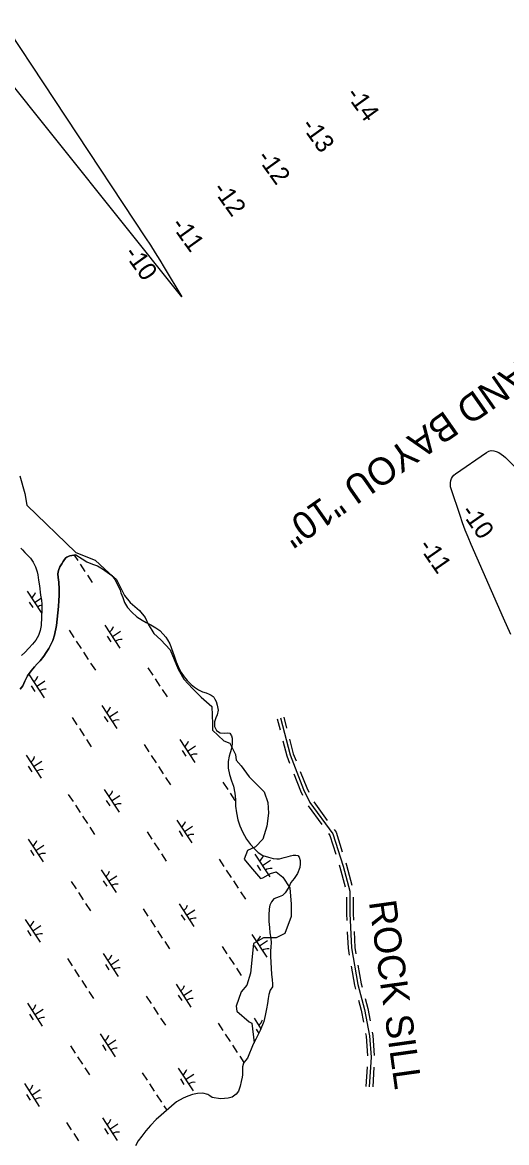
# Model space of a CAD drawing. Extents: x 3945642 to 3966284, y 206476 to 228921.
# Drawn here: x 3957171 to 3958060, y 213998 to 216052 of the extents above; entities that cross this region are included whole.
import ezdxf

# ---------------------------------------------------------------- set-up
doc = ezdxf.new("R2010")
doc.units = 0
for name, color, linetype in [('V-CHAN-NAID', 7, 'Continuous'), ('V-RIVR-EDGE', 7, 'Continuous'), ('V-RIVR-RANG', 7, 'Continuous'), ('V-RRAP-DIKE', 7, 'Continuous'), ('V-RRAP-SILL-IDEN', 7, 'Continuous'), ('V-TOPO-DPTH', 7, 'Continuous'), ('V-TOPO-MINR', 7, 'Continuous'), ('V-TOPO-SHOR', 7, 'Continuous'), ('V-WETL-SWMP', 7, 'Continuous')]:
    doc.layers.add(name, color=color, linetype=linetype)

msp = doc.modelspace()

# ---------------------------------------------------------------- linework, layer by layer
at = {"layer": 'V-RIVR-EDGE'}
for points in [[(3957166.7, 215220.6), (3957175.9, 215187.8), (3957179.8, 215166.7), (3957269.2, 215080)], [(3957269.2, 215080), (3957304.7, 215065.5), (3957330.9, 215041.9), (3957344.1, 215030.1), (3957358.5, 215001.1), (3957369, 214988), (3957386.1, 214973.5), (3957396.6, 214960.4), (3957401.9, 214948.6), (3957412.4, 214931.5), (3957425.6, 214919.7), (3957442.6, 214901.3), (3957457.1, 214865.8), (3957467.6, 214847.4), (3957483.4, 214830.3), (3957499.2, 214814.5), (3957518.9, 214797.4), (3957520.2, 214765.9), (3957520.2, 214754.1), (3957541.2, 214734.4), (3957551.7, 214730.4), (3957562.2, 214709.4), (3957563.5, 214698.9), (3957572.7, 214688.4), (3957587.2, 214668.7), (3957596.4, 214659.5), (3957614.8, 214641.1), (3957621.4, 214621.4), (3957622.7, 214601.6), (3957620.1, 214578), (3957612.2, 214554.3), (3957599, 214539.9), (3957584.6, 214533.3), (3957578, 214517.5), (3957589.8, 214503.1), (3957608.2, 214482), (3957612.2, 214483.4), (3957626.6, 214491.2), (3957637.1, 214493.9), (3957649, 214484.7), (3957662.1, 214465), (3957664.7, 214434.7), (3957664.7, 214412.4), (3957652.9, 214380.9), (3957637.1, 214373), (3957613.5, 214373), (3957595.1, 214362.5), (3957589.8, 214308.6), (3957583.3, 214286.2), (3957572.7, 214274.4), (3957563.5, 214248.1), (3957564.9, 214238.9), (3957587.2, 214219.2), (3957592.5, 214216.6), (3957596.3, 214180.5)]]:
    msp.add_lwpolyline(points, dxfattribs=at)
at = {"layer": 'V-RRAP-DIKE'}
for points in [[(3957638.8, 214775), (3957644.1, 214754.6)], [(3957644.9, 214776.5), (3957662.5, 214708.8), (3957687.2, 214645.5), (3957698.9, 214621.4), (3957741.2, 214563.9), (3957759.9, 214504.7), (3957772, 214459), (3957772, 214417.6), (3957775, 214354.9), (3957787, 214287.6), (3957799, 214242), (3957808, 214193.4), (3957811, 214154.3), (3957807.8, 214100.1)], [(3957650.9, 214778.1), (3957656.2, 214757.8)], [(3957649.4, 214734.3), (3957656.5, 214706.8), (3957661.7, 214693.5)], [(3957661.5, 214737.4), (3957668.4, 214710.7), (3957673.4, 214698)], [(3957669.4, 214673.9), (3957681.4, 214643), (3957685.5, 214634.6)], [(3957681, 214678.4), (3957692.9, 214648), (3957696.8, 214640.1)], [(3957695.8, 214615.1), (3957720.7, 214581.2)], [(3957705.9, 214622.5), (3957730.8, 214588.6)], [(3957733.1, 214564.3), (3957735.6, 214561), (3957746.4, 214526.8)], [(3957743.2, 214571.7), (3957746.9, 214566.7), (3957758.3, 214530.6)], [(3957752.7, 214506.8), (3957753.9, 214502.9), (3957763.5, 214466.6)], [(3957764.6, 214510.6), (3957765.9, 214506.4), (3957775.6, 214469.7)], [(3957765.7, 214447.5), (3957765.7, 214417.4), (3957766.3, 214405.2)], [(3957778.2, 214447.5), (3957778.2, 214417.7), (3957778.8, 214405.8)], [(3957767.3, 214384.2), (3957768.8, 214354.2), (3957771, 214341.6)], [(3957779.8, 214384.8), (3957781.2, 214355.6), (3957783.3, 214343.8)], [(3957774.7, 214321), (3957780.9, 214286.2), (3957782.7, 214279.2)], [(3957787, 214323.1), (3957793.1, 214288.9), (3957794.8, 214282.4)], [(3957788.1, 214258.9), (3957792.9, 214240.6), (3957797, 214218.4)], [(3957800.2, 214262.1), (3957805.1, 214243.3), (3957809.3, 214220.7)], [(3957800.9, 214197.7), (3957801.8, 214192.6), (3957804.5, 214156.6)], [(3957813.1, 214200), (3957814.2, 214194.2), (3957817, 214157.5)], [(3957803.7, 214136.5), (3957801.5, 214100.4)], [(3957816.1, 214135.7), (3957814, 214099.7)]]:
    msp.add_lwpolyline(points, dxfattribs=at)
at = {"layer": 'V-TOPO-DPTH'}
msp.add_line((3957463.9, 215548.9), (3955413.9, 218111.3), dxfattribs=at)
for points in [[(3957104.3, 216100.4), (3957397.5, 215656.7), (3957406.3, 215643.3), (3957415, 215629.7), (3957423.5, 215616.1), (3957431.8, 215602.3), (3957463.9, 215548.9)], [(3958067.2, 214929.3), (3958054.1, 214959.6), (3957994.8, 215094.6), (3957989.3, 215107.8), (3957983.9, 215121), (3957978.9, 215134.5), (3957974.2, 215148), (3957958, 215196.4), (3957957, 215200.2), (3957956.6, 215204.1), (3957956.8, 215207.9), (3957957.4, 215211.8), (3957958.8, 215215.4), (3957960.7, 215218.7), (3957963.1, 215221.6), (3957966.1, 215224.1), (3958022.5, 215263.4), (3958026.9, 215265.6), (3958031.4, 215266.7), (3958036, 215266.5), (3958040.8, 215265.3), (3958045.4, 215263), (3958049.9, 215260.4), (3958053.9, 215257.2), (3958057.8, 215253.8), (3958091.4, 215219.9)]]:
    msp.add_lwpolyline(points, dxfattribs=at)
at = {"layer": 'V-TOPO-MINR'}
for points in [[(3957104.3, 216100.4), (3957397.5, 215656.7), (3957406.3, 215643.3), (3957415, 215629.7), (3957423.5, 215616.1), (3957431.8, 215602.3), (3957463.9, 215548.9)], [(3958067.2, 214929.3), (3958054.1, 214959.6), (3957994.8, 215094.6), (3957989.3, 215107.8), (3957983.9, 215121), (3957978.9, 215134.5), (3957974.2, 215148), (3957958, 215196.4), (3957957, 215200.2), (3957956.6, 215204.1), (3957956.8, 215207.9), (3957957.4, 215211.8), (3957958.8, 215215.4), (3957960.7, 215218.7), (3957963.1, 215221.6), (3957966.1, 215224.1), (3958022.5, 215263.4), (3958026.9, 215265.6), (3958031.4, 215266.7), (3958036, 215266.5), (3958040.8, 215265.3), (3958045.4, 215263), (3958049.9, 215260.4), (3958053.9, 215257.2), (3958057.8, 215253.8), (3958091.4, 215219.9)]]:
    msp.add_lwpolyline(points, dxfattribs=at)
at = {"layer": 'V-TOPO-SHOR'}
for points in [[(3957168.7, 215087.9), (3957171.7, 215084.7), (3957176.1, 215080.1), (3957181.7, 215074.5), (3957186.5, 215069.3), (3957191.3, 215061.9), (3957195.4, 215053.4), (3957198.3, 215044.7), (3957199.7, 215039.1), (3957201.2, 215029.4), (3957202.8, 215018.8), (3957204.6, 215001.6), (3957206.3, 214992.5), (3957207.3, 214985), (3957207.3, 214976.8), (3957206.1, 214945.9), (3957204.3, 214936.7), (3957201.1, 214927.6), (3957195.9, 214919.3), (3957190.1, 214911.6), (3957183, 214904.1), (3957175.9, 214896.4), (3957169.6, 214891)], [(3957269.5, 215075.4), (3957258.3, 215073.5), (3957255.5, 215072.5), (3957253.1, 215071.4), (3957251.1, 215069.9), (3957248.6, 215066.9), (3957246, 215063.2), (3957243.5, 215058.9), (3957240.4, 215053.8), (3957237.6, 215047.1), (3957236.5, 215040.6), (3957237, 215034.1), (3957238, 215025.3), (3957239, 215012.5), (3957239.1, 215001.2), (3957238.2, 214992.1), (3957237.7, 214981), (3957233.7, 214946.1), (3957230.2, 214928), (3957227.3, 214918.7), (3957223.9, 214911.2), (3957219.8, 214903.6), (3957215.1, 214896.5), (3957210.7, 214889.7), (3957204.3, 214881.4), (3957198.8, 214875.4), (3957193.8, 214870), (3957187.7, 214862.9), (3957180.6, 214853.7), (3957176, 214843.9), (3957172.2, 214835.6), (3957167.4, 214829.2)], [(3957630.4, 214283.3), (3957626, 214277), (3957623.5, 214269.5), (3957622, 214261.8), (3957620.8, 214252.5), (3957619.1, 214242.7), (3957617, 214230.8), (3957614.3, 214219.9), (3957607.6, 214203.1), (3957603.5, 214194.4), (3957599.8, 214187.1), (3957595, 214178), (3957584.5, 214152.2), (3957580.7, 214148), (3957576.9, 214143.2), (3957575.1, 214136.6), (3957574.9, 214130.3), (3957574.9, 214122.1), (3957574.4, 214117.9), (3957572.9, 214109.6), (3957571.2, 214101), (3957567.8, 214091.9), (3957563.7, 214086.2), (3957556, 214081.1), (3957549.1, 214079.2), (3957542.3, 214078.4), (3957534.7, 214078.1), (3957519.6, 214080.4), (3957515.3, 214083.6), (3957511.6, 214085.7), (3957502.2, 214088), (3957492.6, 214087.9), (3957483.7, 214085.7), (3957475, 214082.7), (3957466.1, 214079), (3957454, 214072.4), (3957416.6, 214040), (3957406.2, 214028.9), (3957397.7, 214019.2), (3957390.4, 214009.5), (3957384, 214000.9), (3957379.1, 213991.6)]]:
    msp.add_lwpolyline(points, dxfattribs=at)
at = {"layer": 'V-WETL-SWMP'}
for p, q in [((3957266.6, 215074.9), (3957273.1, 215065)), ((3957277.5, 215058.3), (3957286.2, 215044.9)), ((3957290.6, 215038.2), (3957299.4, 215024.8)), ((3957179.9, 215009), (3957207, 214967.7)), ((3957193.6, 214988.1), (3957205.6, 214996)), ((3957183.8, 214988.9), (3957190.4, 214978.9)), ((3957257.2, 214937.4), (3957265.9, 214924)), ((3957322.9, 214946.5), (3957350.3, 214904.7)), ((3957336.6, 214925.6), (3957351.7, 214935.4)), ((3957270.3, 214917.3), (3957279.1, 214903.9)), ((3957326.9, 214926.4), (3957333.5, 214916.3)), ((3957283.5, 214897.2), (3957292.2, 214883.8)), ((3957296.6, 214877.1), (3957305.4, 214863.8)), ((3957183.8, 214855.3), (3957211.2, 214813.5)), ((3957401.8, 214868.4), (3957410.6, 214855.1)), ((3957187.8, 214835.2), (3957194.3, 214825.2)), ((3957197.5, 214834.4), (3957212.6, 214844.3)), ((3957415, 214848.4), (3957423.8, 214835)), ((3957428.1, 214828.3), (3957436.9, 214814.9)), ((3957317.4, 214799.1), (3957344.8, 214757.3)), ((3957262.7, 214777.3), (3957271.5, 214763.9)), ((3957321.4, 214779), (3957327.9, 214769)), ((3957331.1, 214778.2), (3957346.2, 214788.1)), ((3957275.9, 214757.2), (3957284.6, 214743.8)), ((3957289, 214737.1), (3957297.8, 214723.7)), ((3957394.7, 214727.5), (3957403.4, 214714.1)), ((3957460.5, 214736.6), (3957487.9, 214694.8)), ((3957178.3, 214708), (3957205.7, 214666.1)), ((3957407.8, 214707.4), (3957416.6, 214694)), ((3957464.4, 214716.5), (3957471, 214706.4)), ((3957474.2, 214715.7), (3957489.2, 214725.5)), ((3957182.2, 214687.8), (3957188.8, 214677.8)), ((3957192, 214687.1), (3957207, 214696.9)), ((3957421, 214687.3), (3957429.7, 214673.9)), ((3957434.1, 214667.2), (3957442.9, 214653.8)), ((3957321.3, 214645.4), (3957348.7, 214603.6)), ((3957539.4, 214658.5), (3957548.1, 214645.1)), ((3957255.5, 214636.3), (3957264.3, 214622.9)), ((3957325.3, 214625.3), (3957331.9, 214615.3)), ((3957335, 214624.5), (3957350.1, 214634.4)), ((3957552.5, 214638.4), (3957561.3, 214625.1)), ((3957268.7, 214616.2), (3957277.5, 214602.8)), ((3957281.8, 214596.2), (3957290.6, 214582.8)), ((3957454.9, 214589.2), (3957482.3, 214547.4)), ((3957295, 214576.1), (3957303.8, 214562.7)), ((3957400.2, 214567.4), (3957409, 214554)), ((3957458.9, 214569.1), (3957465.4, 214559)), ((3957468.6, 214568.3), (3957483.7, 214578.2)), ((3957182.2, 214554.3), (3957209.6, 214512.5)), ((3957195.9, 214533.4), (3957210.9, 214543.2)), ((3957413.4, 214547.3), (3957422.1, 214533.9)), ((3957186.1, 214534.2), (3957192.7, 214524.1)), ((3957426.5, 214527.2), (3957435.3, 214513.8)), ((3957598, 214526.7), (3957625.4, 214484.8)), ((3957532.2, 214517.5), (3957541, 214504.2)), ((3957601.9, 214506.5), (3957608.5, 214496.5)), ((3957611.7, 214505.7), (3957626.7, 214515.6)), ((3957315.8, 214498.1), (3957343.2, 214456.2)), ((3957329.5, 214477.1), (3957344.5, 214487)), ((3957545.3, 214497.5), (3957554.1, 214484.1)), ((3957261.1, 214476.2), (3957269.9, 214462.8)), ((3957319.7, 214477.9), (3957326.3, 214467.9)), ((3957558.5, 214477.4), (3957567.3, 214464)), ((3957274.2, 214456.1), (3957283, 214442.8)), ((3957571.6, 214457.3), (3957580.4, 214443.9)), ((3957287.4, 214436.1), (3957296.2, 214422.7)), ((3957393.1, 214426.4), (3957401.8, 214413)), ((3957458.8, 214435.5), (3957486.2, 214393.7)), ((3957472.5, 214414.6), (3957487.6, 214424.5)), ((3957176.6, 214406.9), (3957204, 214365.1)), ((3957406.2, 214406.3), (3957415, 214392.9)), ((3957462.8, 214415.4), (3957469.4, 214405.3)), ((3957180.6, 214386.8), (3957187.2, 214376.7)), ((3957190.3, 214386), (3957205.4, 214395.9)), ((3957419.4, 214386.2), (3957428.1, 214372.8)), ((3957592.4, 214379.3), (3957619.8, 214337.5)), ((3957432.5, 214366.2), (3957441.3, 214352.8)), ((3957537.7, 214357.4), (3957546.5, 214344.1)), ((3957596.4, 214359.2), (3957603, 214349.1)), ((3957606.1, 214358.4), (3957621.2, 214368.2)), ((3957319.7, 214344.4), (3957347.1, 214302.5)), ((3957550.9, 214337.4), (3957559.7, 214324)), ((3957253.9, 214335.2), (3957262.7, 214321.8)), ((3957323.7, 214324.2), (3957330.2, 214314.2)), ((3957333.4, 214323.4), (3957348.5, 214333.3)), ((3957564, 214317.3), (3957572.8, 214303.9)), ((3957267.1, 214315.2), (3957275.8, 214301.8)), ((3957280.2, 214295.1), (3957289, 214281.7)), ((3957453.3, 214288.1), (3957480.7, 214246.3)), ((3957467, 214267.2), (3957482.1, 214277.1)), ((3957293.4, 214275), (3957302.1, 214261.6)), ((3957398.6, 214266.3), (3957407.4, 214252.9)), ((3957457.3, 214268), (3957463.8, 214258)), ((3957180.6, 214253.2), (3957208, 214211.4)), ((3957194.3, 214232.3), (3957209.3, 214242.2)), ((3957411.8, 214246.2), (3957420.5, 214232.8)), ((3957184.5, 214233.1), (3957191.1, 214223)), ((3957424.9, 214226.1), (3957433.7, 214212.8)), ((3957530.6, 214216.5), (3957539.3, 214203.1)), ((3957596.4, 214225.6), (3957608.9, 214206.4)), ((3957314.2, 214197), (3957341.6, 214155.2)), ((3957543.7, 214196.4), (3957552.5, 214183)), ((3957600.3, 214205.5), (3957605.2, 214198)), ((3957259.5, 214175.1), (3957268.2, 214161.8)), ((3957318.1, 214176.9), (3957324.7, 214166.8)), ((3957327.9, 214176.1), (3957342.9, 214185.9)), ((3957556.9, 214176.3), (3957565.6, 214162.9)), ((3957272.6, 214155.1), (3957281.4, 214141.7)), ((3957570, 214156.2), (3957577.8, 214144.4)), ((3957285.8, 214135), (3957294.5, 214121.6)), ((3957457.2, 214134.4), (3957484.6, 214092.6)), ((3957391.4, 214125.3), (3957400.2, 214111.9)), ((3957461.2, 214114.3), (3957467.8, 214104.3)), ((3957470.9, 214113.5), (3957486, 214123.4)), ((3957175, 214105.8), (3957202.4, 214064)), ((3957188.7, 214084.9), (3957203.8, 214094.8)), ((3957404.6, 214105.2), (3957413.4, 214091.9)), ((3957179, 214085.7), (3957185.6, 214075.7)), ((3957417.7, 214085.2), (3957426.5, 214071.8)), ((3957430.9, 214065.1), (3957436.2, 214057)), ((3957252.3, 214034.2), (3957261.1, 214020.8)), ((3957318.1, 214043.3), (3957345.5, 214001.5)), ((3957331.8, 214022.4), (3957346.8, 214032.2)), ((3957265.5, 214014.1), (3957274.2, 214000.7)), ((3957322.1, 214023.2), (3957328.6, 214013.1))]:
    msp.add_line(p, q, dxfattribs=at)
for points in [[(3957168.7, 215087.9), (3957171.7, 215084.7), (3957176.1, 215080.1), (3957181.7, 215074.5), (3957186.5, 215069.3), (3957191.3, 215061.9), (3957195.4, 215053.4), (3957198.3, 215044.7), (3957199.7, 215039.1), (3957201.2, 215029.4), (3957202.8, 215018.8), (3957204.6, 215001.6), (3957206.3, 214992.5), (3957207.3, 214985), (3957207.3, 214976.8), (3957206.1, 214945.9), (3957204.3, 214936.7), (3957201.1, 214927.6), (3957195.9, 214919.3), (3957190.1, 214911.6), (3957183, 214904.1), (3957175.9, 214896.4), (3957169.6, 214891)], [(3957167.4, 214829.2), (3957172.2, 214835.6), (3957176, 214843.9), (3957180.6, 214853.7), (3957187.7, 214862.9), (3957193.8, 214870), (3957198.8, 214875.4), (3957204.3, 214881.4), (3957210.7, 214889.7), (3957215.1, 214896.5), (3957219.8, 214903.6), (3957223.9, 214911.2), (3957227.3, 214918.7), (3957230.2, 214928), (3957233.7, 214946.1), (3957237.7, 214981), (3957238.2, 214992.1), (3957239.1, 215001.2), (3957239, 215012.5), (3957238, 215025.3), (3957237, 215034.1), (3957236.5, 215040.6), (3957237.6, 215047.1), (3957240.4, 215053.8), (3957243.5, 215058.9), (3957246, 215063.2), (3957248.6, 215066.9), (3957251.1, 215069.9), (3957253.1, 215071.4), (3957255.5, 215072.5), (3957258.3, 215073.5), (3957269.5, 215075.4), (3957281, 215068.3), (3957289.9, 215062.7), (3957300.1, 215058.4), (3957309.5, 215055.4), (3957318.4, 215049.7), (3957335.4, 215037.5), (3957341.2, 215030.2), (3957346.8, 215020), (3957350.7, 215010.8), (3957352.3, 215005.9), (3957355.4, 214997.3), (3957358.8, 214988.2), (3957364, 214979.1), (3957371.9, 214970.4), (3957381.3, 214961.8), (3957390.9, 214955.7), (3957398.7, 214951.6), (3957407.2, 214947), (3957416.1, 214941.7), (3957423.4, 214936.7), (3957429.4, 214930.3), (3957434.3, 214924.6), (3957437.8, 214919.6), (3957441.8, 214912.4), (3957447.7, 214896.8), (3957449.7, 214890.1), (3957453.5, 214879.1), (3957457.1, 214870.5), (3957462.7, 214859.9), (3957468.3, 214851.7), (3957473.6, 214845.2), (3957481.1, 214837.8), (3957487, 214832.6), (3957494.5, 214828.1), (3957501.9, 214824.6), (3957508.3, 214822.2), (3957513.8, 214820.2), (3957517.7, 214818.3), (3957521.4, 214816), (3957522.5, 214814.6), (3957524.6, 214810.7), (3957526.7, 214806.3), (3957528.8, 214799.8), (3957530.3, 214790.5), (3957528.8, 214782.4), (3957526.2, 214776.6), (3957523.8, 214769.6), (3957523.7, 214760.7), (3957527.7, 214753.4)], [(3957527.7, 214753.4), (3957534.4, 214749.4), (3957542, 214748.8), (3957548.4, 214749.2), (3957552.1, 214748.5), (3957555.1, 214743.9), (3957556.1, 214739.2), (3957556.5, 214728.8), (3957554.8, 214720.5), (3957552.5, 214712.4), (3957550.9, 214706.5), (3957549.2, 214696.4), (3957549, 214684.2), (3957551.2, 214672.8), (3957554.8, 214661.3), (3957558.9, 214651.3), (3957561.4, 214638.2), (3957562.2, 214626.7), (3957562.6, 214614.8), (3957563.9, 214602.2), (3957566.4, 214589.8), (3957570.4, 214578.7), (3957575, 214567.8), (3957582.7, 214554.4), (3957589.9, 214544.6), (3957596.9, 214536.6), (3957604.1, 214529.9), (3957612.6, 214524.3), (3957622.6, 214520.8), (3957631.4, 214518.7), (3957638.1, 214517.8), (3957643, 214518.3), (3957651.5, 214520.4), (3957658.7, 214522.2), (3957663.3, 214523.7), (3957668.2, 214524.8), (3957673.3, 214524.9), (3957677, 214523.9), (3957679.4, 214520.8), (3957680.9, 214515.2), (3957681, 214508.6), (3957680.4, 214501.9), (3957676.1, 214491.2), (3957669.7, 214482.2), (3957663.9, 214474.4), (3957660, 214466.1), (3957653.7, 214455.4), (3957648.3, 214451.1), (3957642.5, 214448.2), (3957637.8, 214446.7), (3957632.5, 214444.6), (3957628.1, 214439.3), (3957625.4, 214432.9), (3957624.2, 214426.5), (3957623.6, 214414.6), (3957623.7, 214403), (3957624.5, 214392.1), (3957625.6, 214382.6), (3957627.1, 214372.3), (3957627.5, 214363.3), (3957627.1, 214357.2), (3957626.6, 214348.3), (3957626.8, 214339.3), (3957627.7, 214316.9), (3957628.5, 214306.5), (3957629.7, 214296.2), (3957630.2, 214289), (3957630.4, 214283.3), (3957626, 214277), (3957623.5, 214269.5), (3957622, 214261.8), (3957620.8, 214252.5), (3957619.2, 214242.7), (3957617, 214230.8), (3957614.3, 214219.9), (3957607.6, 214203.1), (3957603.5, 214194.4), (3957599.8, 214187.1), (3957595, 214178), (3957584.5, 214152.2), (3957580.7, 214148), (3957576.9, 214143.2), (3957575.1, 214136.6), (3957574.9, 214130.3), (3957574.9, 214122.1), (3957574.4, 214117.9), (3957572.9, 214109.6), (3957571.2, 214101), (3957567.8, 214091.9), (3957563.7, 214086.2), (3957556, 214081.1), (3957549.1, 214079.2), (3957542.3, 214078.4), (3957534.7, 214078.1), (3957519.6, 214080.4), (3957515.3, 214083.6), (3957511.6, 214085.7), (3957502.2, 214088), (3957492.6, 214087.9), (3957483.7, 214085.7), (3957475, 214082.7)], [(3957475, 214082.7), (3957466.1, 214079), (3957454, 214072.4), (3957416.6, 214040), (3957406.2, 214028.9), (3957397.7, 214019.2), (3957390.4, 214009.5), (3957384, 214000.9), (3957379.1, 213991.6)]]:
    msp.add_lwpolyline(points, dxfattribs=at)
for centre, start, end in [((3957178.6, 215011.4), 302.4575, 344.0011), ((3957208.9, 214965.2), 95.2585, 124.0011), ((3957321.7, 214948.8), 302.4575, 344.0011), ((3957352, 214902.6), 82.4574, 124.0011), ((3957182.6, 214857.7), 302.4575, 344.0011), ((3957212.8, 214811.5), 82.4574, 124.0011), ((3957316.2, 214801.4), 302.4575, 344.0011), ((3957346.4, 214755.2), 82.4574, 124.0011), ((3957459.2, 214738.9), 302.4575, 344.0011), ((3957489.5, 214692.7), 82.4574, 124.0011), ((3957177, 214710.3), 302.4575, 344.0011), ((3957207.3, 214664.1), 82.4574, 124.0011), ((3957320.1, 214647.8), 302.4575, 344.0011), ((3957350.4, 214601.5), 82.4574, 124.0011), ((3957453.7, 214591.5), 302.4575, 344.0011), ((3957483.9, 214545.3), 82.4574, 124.0011), ((3957181, 214556.6), 302.4575, 344.0011), ((3957211.2, 214510.4), 82.4574, 124.0011), ((3957596.8, 214529), 302.4575, 343.3994), ((3957314.5, 214500.4), 302.4575, 344.0011), ((3957627, 214482.8), 82.4574, 124.0011), ((3957344.8, 214454.2), 82.4574, 124.0011), ((3957457.6, 214437.8), 302.4575, 344.0011), ((3957175.4, 214409.2), 302.4575, 344.0011), ((3957487.9, 214391.6), 82.4574, 124.0011), ((3957205.7, 214363), 82.4574, 124.0011), ((3957591.2, 214381.6), 302.4575, 344.0011), ((3957318.5, 214346.7), 302.4575, 344.0011), ((3957621.5, 214335.4), 82.4574, 124.0011), ((3957348.7, 214300.5), 82.4574, 124.0011), ((3957452.1, 214290.5), 302.4575, 344.0011), ((3957482.3, 214244.2), 82.4574, 124.0011), ((3957179.3, 214255.5), 302.4575, 344.0011), ((3957209.6, 214209.3), 82.4574, 124.0011), ((3957595.1, 214227.9), 302.4575, 344.0011), ((3957312.9, 214199.3), 302.4575, 344.0011), ((3957343.2, 214153.1), 82.4574, 124.0011), ((3957456, 214136.8), 302.4575, 344.0011), ((3957173.8, 214108.2), 302.4575, 344.0011), ((3957486.3, 214090.6), 82.4574, 124.0011), ((3957204.1, 214061.9), 82.4574, 124.0011), ((3957316.9, 214045.6), 302.4575, 344.0011), ((3957347.1, 213999.4), 82.4574, 124.0011)]:
    msp.add_arc(centre, 17.6, start, end, dxfattribs=at)

# ---------------------------------------------------------------- texts
at = {"layer": 'V-CHAN-NAID'}
msp.add_text('OLD GRAND BAYOU "10"', height=50, rotation=214.9873, dxfattribs=at).set_placement((3958288, 215580))
at = {"layer": 'V-RIVR-RANG'}
for s, rotation, p in [('-14', 305.6956, (3957763.5, 215919.7)), ('-13', 305.6956, (3957681.3, 215862.8)), ('-12', 305.6956, (3957600.2, 215804.2)), ('-12', 305.6956, (3957519, 215745.9)), ('-11', 305.6956, (3957442.6, 215680.8)), ('-10', 305.6956, (3957356.5, 215627.9)), ('-10', 304.7432, (3957974.4, 215154.5)), ('-11', 304.7432, (3957896.6, 215091.5))]:
    msp.add_text(s, height=33.5, rotation=rotation, dxfattribs=at).set_placement(p)
at = {"layer": 'V-RRAP-SILL-IDEN'}
msp.add_text('ROCK SILL', height=50, rotation=277.9222, dxfattribs=at).set_placement((3957806.9, 214439.1))

doc.saveas('drawing.dxf')
